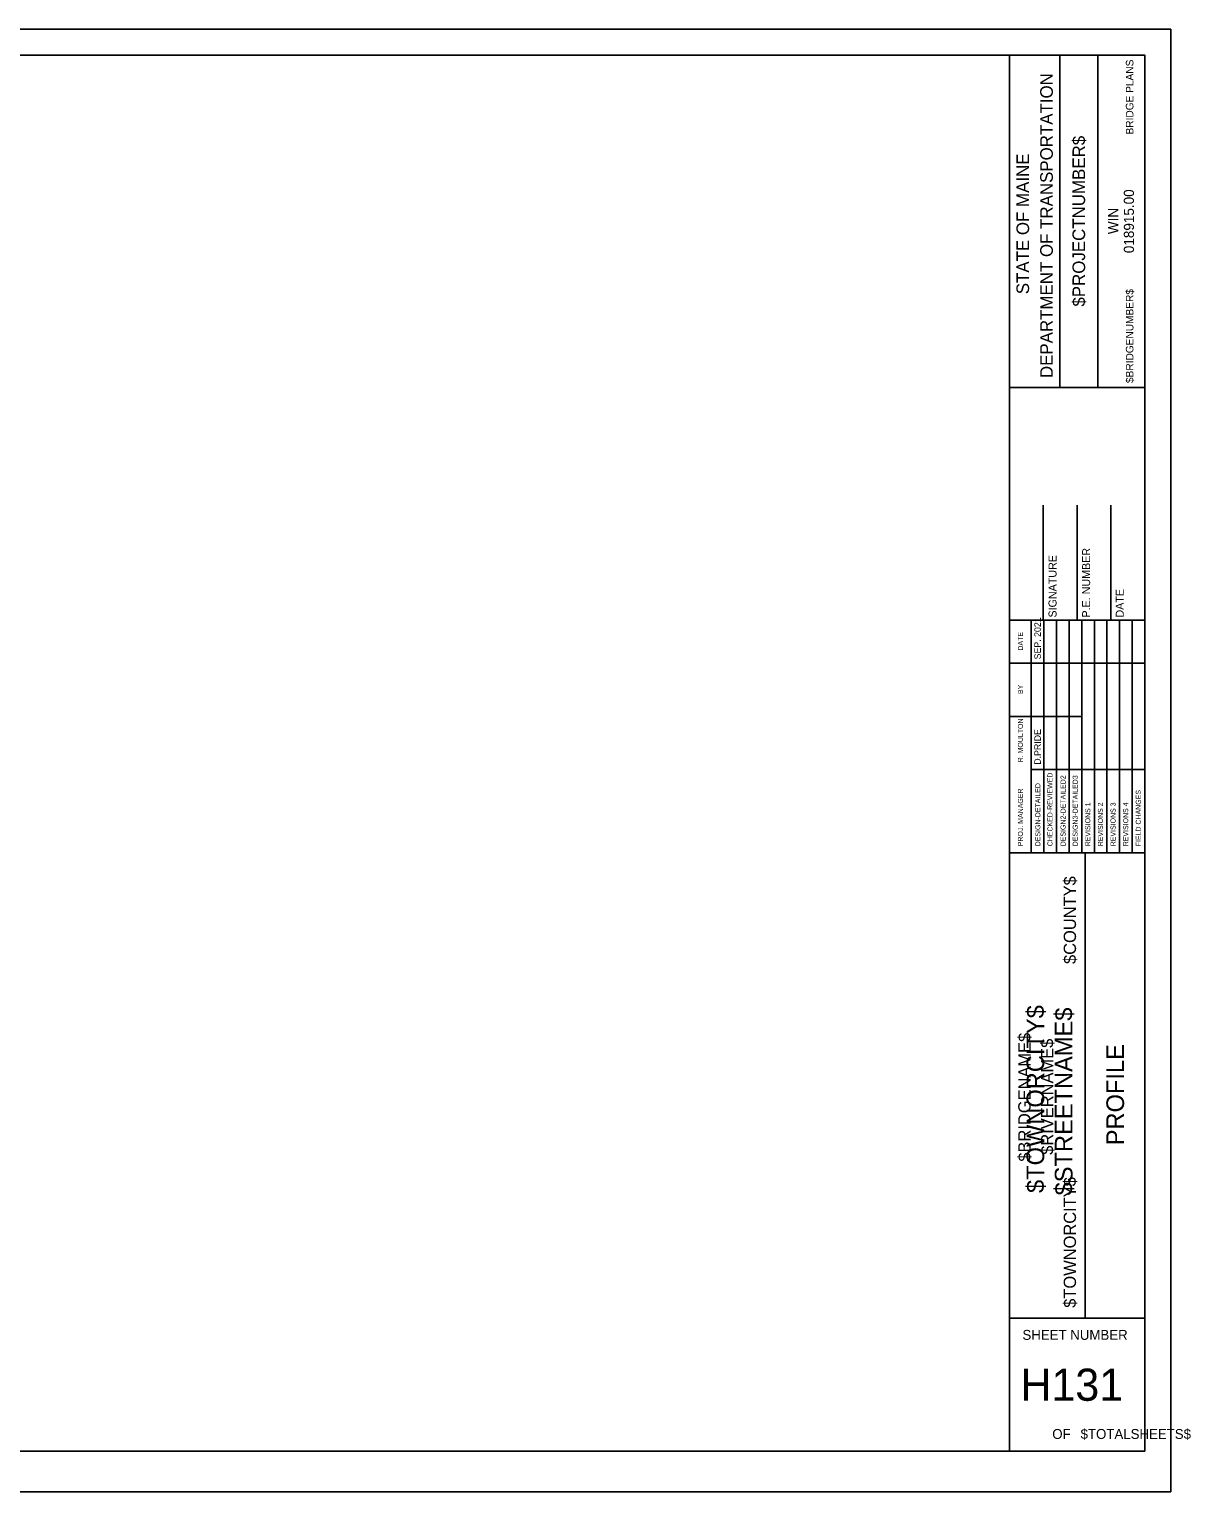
# Model space of a CAD drawing. Extents: x 337485 to 338343, y 9985 to 10525.
# Drawn here: x 337914 to 338343, y 9985 to 10525 of the extents above; entities that cross this region are included whole.
import ezdxf

# ---------------------------------------------------------------- set-up
doc = ezdxf.new("R2010")
doc.units = 0
for name, color, linetype in [('BORDER', 7, 'Continuous'), ('BRIDGE_TITLE', 7, 'Continuous'), ('CLIPS', 7, 'Continuous'), ('HIGHWAY_TITLE', 7, 'Continuous'), ('PLOT BOUNDARY', 7, 'Continuous')]:
    doc.layers.add(name, color=color, linetype=linetype)

msp = doc.modelspace()

# ---------------------------------------------------------------- linework, layer by layer
at = {"layer": 'BORDER'}
for p, q in [((338275.85, 10000), (338275.85, 10515)), ((338294.5, 10392.37), (338294.5, 10514.99)), ((338308.47, 10392.37), (338308.47, 10514.99)), ((338275.86, 10392.35), (338325.85, 10392.35)), ((338288.35, 10306.56), (338288.35, 10348.98)), ((338300.85, 10306.56), (338300.85, 10348.98)), ((338313.35, 10306.56), (338313.35, 10348.98)), ((338275.85, 10306.56), (338325.85, 10306.56)), ((338275.85, 10220.73), (338325.85, 10220.73)), ((338303.81, 10049.06), (338303.81, 10220.73)), ((338275.85, 10049.06), (338325.85, 10049.06))]:
    msp.add_line(p, q, dxfattribs=at)
msp.add_lwpolyline([(337525.85, 10515), (338325.85, 10515), (338325.85, 10000), (337525.85, 10000)], close=True, dxfattribs=at)
for points in [[(338283.93, 10290.62), (338283.93, 10306.56)], [(338288.59, 10220.74), (338288.59, 10306.56)], [(338293.25, 10306.56), (338293.25, 10220.74)], [(338297.91, 10220.74), (338297.91, 10306.56)], [(338302.57, 10220.74), (338302.57, 10306.56)], [(338307.22, 10220.74), (338307.22, 10306.56)], [(338311.88, 10220.74), (338311.88, 10306.56)], [(338316.54, 10220.74), (338316.54, 10306.56)], [(338321.2, 10220.74), (338321.2, 10306.56)], [(338283.93, 10220.74), (338283.93, 10303.1)], [(338275.85, 10290.62), (338325.85, 10290.62)], [(338275.85, 10271), (338283.93, 10271)], [(338283.93, 10271), (338302.56, 10271)], [(338283.93, 10251.38), (338325.85, 10251.38)]]:
    msp.add_lwpolyline(points, dxfattribs=at)
at = {"layer": 'CLIPS'}
msp.add_lwpolyline([(337525.85, 10000), (338275.85, 10000), (338275.85, 10515), (337525.85, 10515)], close=True, dxfattribs=at)
at = {"layer": 'PLOT BOUNDARY'}
msp.add_lwpolyline([(337485.39, 9985), (338335.39, 9985), (338335.39, 10524.52), (337485.39, 10524.52)], close=True, dxfattribs=at)

# ---------------------------------------------------------------- texts
at = {"layer": 'BORDER'}
for s, height, rotation, p in [('DEPARTMENT OF TRANSPORTATION', 4.6588, 90, (338291.89, 10395.84)), ('$PROJECTNUMBER$', 4.6588, 90, (338303.81, 10422.2)), ('STATE OF MAINE', 4.6588, 90, (338283.13, 10426.77)), ('018915.00', 3.726, 90, (338321.83, 10441.91)), ('WIN', 3.726, 90, (338316.04, 10448.93)), ('P.E. NUMBER', 2.9528, 90, (338305.66, 10307.5)), ('SIGNATURE', 2.953, 90, (338293.26, 10307.5)), ('DATE', 2.953, 90, (338318.06, 10307.5)), ('SEP. 2021', 2.423, 90, (338287.47, 10292.07)), ('DATE', 1.857, 90, (338280.87, 10295.31)), ('BY', 1.857, 90, (338280.87, 10279.27)), ('R. MOULTON', 1.864, 90, (338280.87, 10254.09)), ('D.PRIDE', 2.423, 90, (338287.47, 10253.21)), ('DESIGN-DETAILED', 1.8637, 90, (338287.29, 10223.12)), ('CHECKED-REVIEWED', 1.8637, 90, (338291.76, 10223.12)), ('DESIGN2-DETAILED2', 1.8637, 90, (338296.6, 10223.12)), ('DESIGN3-DETAILED3', 1.8637, 90, (338301.07, 10223.12)), ('PROJ. MANAGER', 1.8637, 90, (338280.87, 10223.12)), ('FIELD CHANGES', 1.8637, 90, (338324.37, 10223.12)), ('REVISIONS 1', 1.8637, 90, (338305.73, 10223.12)), ('REVISIONS 2', 1.8637, 90, (338310.39, 10223.12)), ('REVISIONS 3', 1.8637, 90, (338315.05, 10223.12)), ('REVISIONS 4', 1.8637, 90, (338319.71, 10223.12)), ('PROFILE', 6.521, 90, (338318.18, 10112.81)), ('SHEET NUMBER', 3.6554, 360, (338280.68, 10041.04)), ('OF', 3.655, 360, (338291.69, 10004.48)), ('$TOTALSHEETS$', 3.6554, 360, (338302.14, 10004.48))]:
    msp.add_text(s, height=height, rotation=rotation, dxfattribs=at).set_placement(p)
msp.add_text('H131', height=11.867, dxfattribs=at).set_placement((338279.91, 10018.55))
at = {"layer": 'BRIDGE_TITLE'}
for s, height, p in [('BRIDGE PLANS', 2.795, (338321.64, 10485.69)), ('$BRIDGENUMBER$', 2.795, (338321.64, 10394)), ('$COUNTY$', 4.536, (338300.45, 10179.69)), ('$BRIDGENAME$', 4.5358, (338283.68, 10106.78)), ('$RIVERNAME$', 4.5358, (338292.07, 10109.31)), ('$TOWNORCITY$', 4.5358, (338300.45, 10052.86))]:
    msp.add_text(s, height=height, rotation=90, dxfattribs=at).set_placement(p)
at = {"layer": 'HIGHWAY_TITLE'}
for s, p in [('$TOWNORCITY$', (338288.71, 10095.21)), ('$STREETNAME$', (338299.15, 10094.32))]:
    msp.add_text(s, height=6.5214, rotation=90, dxfattribs=at).set_placement(p)

doc.saveas('drawing.dxf')
